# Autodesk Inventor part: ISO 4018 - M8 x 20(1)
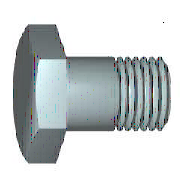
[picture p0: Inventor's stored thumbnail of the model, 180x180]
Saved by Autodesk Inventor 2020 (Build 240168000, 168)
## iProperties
Created: 2019-01
Part Number: ISO 4018 - M8 x 20(1)
Material: Ocel
Description: Šrouby se šestihrannou hlavou se závitem k hlavě. Výrobní třída C
Document SubType Name: Modeling
Standard: ISO 4018
Designer: doma
Standard Revision: Fourth edition 2011-04-01
Standards Organization: ISO
Language: cs-CZ
Size Designation: M8 x 20
Categories: <MemberInstance><Categories><Category DisplayName="Spojovací materiál" InternalName="e4da775c-781d-43d5-af7c-5136215cf5a6" Mnemonic="FSTN"><Category DisplayName
Density: 7.85 g/cm^3
Appearance: Plech
IsCustomPart: 0
Author: doma
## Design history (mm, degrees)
node "WorkPlane1"
node "WorkPoint1"
node "MSC_A1"
node "MSC_PF1"
node "MSC_PT1"
body "Solid1"
node "Náčrt1"
sketch "Náčrt2"
  geometry: L1 (-6.5, 3.753)-(-6.5, -3.753); L2 (0, 7.505)-(-6.5, 3.753); L3 (6.5, 3.753)-(0, 7.505); L4 (6.5, -3.753)-(6.5, 3.753); L5 (0, -7.505)-(6.5, -3.753); L6 (-6.5, -3.753)-(0, -7.505); C1 r 6.5 at (0, 0); 1 further point
  constraints: 12 end point, 6 tangent, 2 parallel, 2 vertical, 1 centre point
  dimensions: "d1" = 13 diameter of C1 (= ParS); "d29" = 0 distance of point (0, 0) C1.centre; "d30" = 0 distance of C1.centre point (0, 0)
extrude "Vysunutí1" new body sketch "Náčrt2" distance "d6" = 5.3 (= ParK); taper "d7" = 0 deg
revolve "Rotace1" stored, may be unused: angle "d14" = 360 deg
revolve "Rotace2" stored, may be unused: angle "d21" = 360 deg
chamfer "Zkosení1" distance "d22" = 0.625 (= 0.5 x PTC); stored, may be unused: second distance "d23" = 0.625 (= 0.5 x PTC), angle "d39" = 45 deg
fillet "Zaoblení1" dims "d24" = 0.4 (= r)
feature "Závit1" dims "d32" = 0, "b" = 17.5 (= NLG - 2 x PTC)
sketch "Náčrt3"
  geometry: L1 (6.5, 5.3)-(7.605, 5.3); L2 (7.605, 4.662)-(6.5, 5.3); L3 (7.605, 5.3)-(7.605, 4.662); L4 (0, -1.06)-(0, 6.36) reference; L5 (7.505, 0)-(7.505, 5.3) reference
  constraints: 6 end point, 1 horizontal, 1 vertical
  dimensions: "d25" = 0.1 distance between parallel lines of L5 L3; "d26" = 0 distance from line of L5.end L1; "d27" = 60 deg angle of L3 L2; "d28" = 6.5 distance from line of L4 L1.start (= 0.5 x ParS)
sketch "Náčrt4"
  geometry: L1 (0, -20)-(0, 0); L2 (-4, -20)-(0, -20); L3 (-4, 0)-(-4, -20); L4 (0, 0)-(-4, 0); L5 (0, -20)-(0, 0); L6 (-4.8, 0)-(0.8, 0) reference; L7 (0, -24)-(0, 4) reference
  constraints: 10 end point, 2 horizontal, 2 vertical
  dimensions: "d18" = 4 distance of L1.start L2.start (= 0.5 x NND); "d20" = 20 distance of L3.start L2.start (= NLG); "d33" = 0 distance between parallel lines of L7 L1; "d34" = 0 distance between parallel lines of L6 L4
other parameters: "NND" = 8 [user parameter; used in 2 equation terms], "NLG" = 20 [user parameter; used in 2 equation terms], "PTC" = 1.25 [user parameter; used in 3 equation terms], "ParK" = 5.3 [user parameter; used in 1 equation term], "ParS" = 13 [user parameter; used in 3 equation terms], "msp_es" = 7.50577 (= 0.577367 x ParS) [user parameter], "r" = 0.4 [user parameter; used in 1 equation term], "d2" = 15 (derived), "d4" = 17.32102 (derived), "d8" = 15 (derived), "d10" = 0 (derived), "d12" = 30 deg (derived), "d15" = 0 (derived), "d37" = 0, "d38" = 0, "d40" = 0, "d41" = 0, "d42" = 0, "THREADDIA" = 8 (= NND) [user parameter]
